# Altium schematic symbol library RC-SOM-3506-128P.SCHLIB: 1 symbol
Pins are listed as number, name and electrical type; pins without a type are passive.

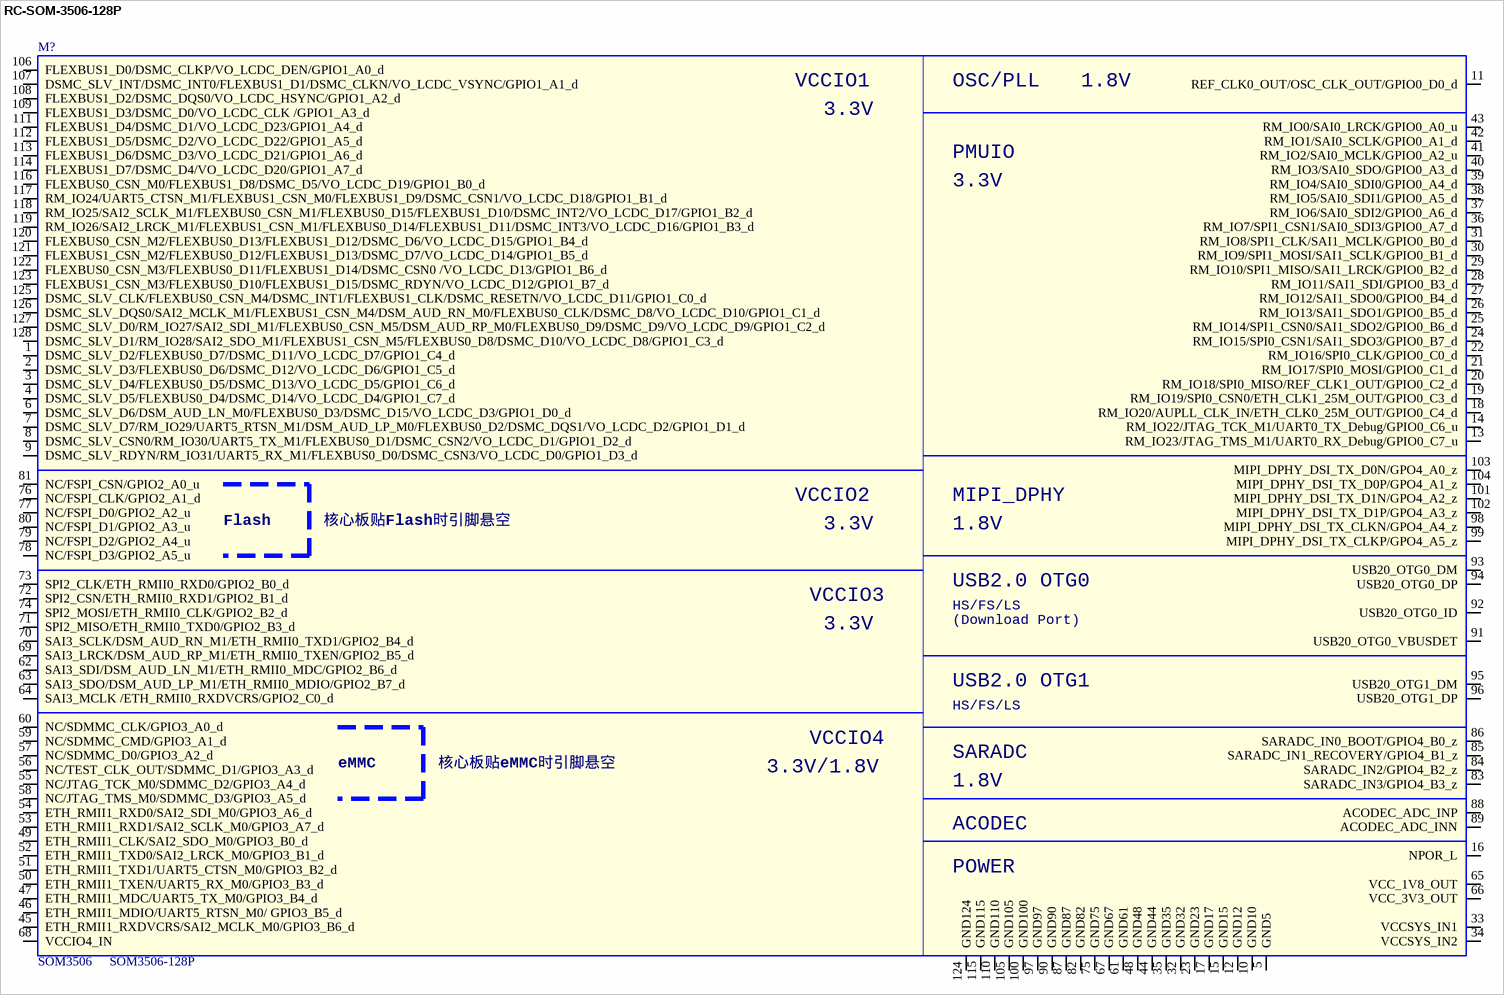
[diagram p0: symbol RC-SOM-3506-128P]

## RC-SOM-3506-128P
designator M?, comment SOM3506  PCB Footprint: SOM3506-128P
footprint SOM3506-128P
footprint SOM3506-128P
pins: 1 DSMC_SLV_D2/FLEXBUS0_D7/DSMC_D11/VO_LCDC_D7/GPIO1_C4_d, 2 DSMC_SLV_D3/FLEXBUS0_D6/DSMC_D12/VO_LCDC_D6/GPIO1_C5_d, 3 DSMC_SLV_D4/FLEXBUS0_D5/DSMC_D13/VO_LCDC_D5/GPIO1_C6_d, 4 DSMC_SLV_D5/FLEXBUS0_D4/DSMC_D14/VO_LCDC_D4/GPIO1_C7_d, 5 GND5, 6 DSMC_SLV_D6/DSM_AUD_LN_M0/FLEXBUS0_D3/DSMC_D15/VO_LCDC_D3/GPIO1_D0_d, 7 DSMC_SLV_D7/RM_IO29/UART5_RTSN_M1/DSM_AUD_LP_M0/FLEXBUS0_D2/DSMC_DQS1/VO_LCDC_D2/GPIO1_D1_d, 8 DSMC_SLV_CSN0/RM_IO30/UART5_TX_M1/FLEXBUS0_D1/DSMC_CSN2/VO_LCDC_D1/GPIO1_D2_d, 9 DSMC_SLV_RDYN/RM_IO31/UART5_RX_M1/FLEXBUS0_D0/DSMC_CSN3/VO_LCDC_D0/GPIO1_D3_d, 10 GND10, 11 REF_CLK0_OUT/OSC_CLK_OUT/GPIO0_D0_d, 12 GND12, 13 RM_IO23/JTAG_TMS_M1/UART0_RX_Debug/GPIO0_C7_u, 14 RM_IO22/JTAG_TCK_M1/UART0_TX_Debug/GPIO0_C6_u, 15 GND15, 16 NPOR_L, 17 GND17, 18 RM_IO20/AUPLL_CLK_IN/ETH_CLK0_25M_OUT/GPIO0_C4_d, 19 RM_IO19/SPI0_CSN0/ETH_CLK1_25M_OUT/GPIO0_C3_d, 20 RM_IO18/SPI0_MISO/REF_CLK1_OUT/GPIO0_C2_d, 21 RM_IO17/SPI0_MOSI/GPIO0_C1_d, 22 RM_IO16/SPI0_CLK/GPIO0_C0_d, 23 GND23, 24 RM_IO15/SPI0_CSN1/SAI1_SDO3/GPIO0_B7_d, 25 RM_IO14/SPI1_CSN0/SAI1_SDO2/GPIO0_B6_d, 26 RM_IO13/SAI1_SDO1/GPIO0_B5_d, 27 RM_IO12/SAI1_SDO0/GPIO0_B4_d, 28 RM_IO11/SAI1_SDI/GPIO0_B3_d, 29 RM_IO10/SPI1_MISO/SAI1_LRCK/GPIO0_B2_d, 30 RM_IO9/SPI1_MOSI/SAI1_SCLK/GPIO0_B1_d, 31 RM_IO8/SPI1_CLK/SAI1_MCLK/GPIO0_B0_d, 32 GND32, 33 VCCSYS_IN1, 34 VCCSYS_IN2, 35 GND35, 36 RM_IO7/SPI1_CSN1/SAI0_SDI3/GPIO0_A7_d, 37 RM_IO6/SAI0_SDI2/GPIO0_A6_d, 38 RM_IO5/SAI0_SDI1/GPIO0_A5_d, 39 RM_IO4/SAI0_SDI0/GPIO0_A4_d, 40 RM_IO3/SAI0_SDO/GPIO0_A3_d, 41 RM_IO2/SAI0_MCLK/GPIO0_A2_u, 42 RM_IO1/SAI0_SCLK/GPIO0_A1_d, 43 RM_IO0/SAI0_LRCK/GPIO0_A0_u, 44 GND44, 45 ETH_RMII1_RXDVCRS/SAI2_MCLK_M0/GPIO3_B6_d, 46 ETH_RMII1_MDIO/UART5_RTSN_M0/ GPIO3_B5_d, 47 ETH_RMII1_MDC/UART5_TX_M0/GPIO3_B4_d, 48 GND48, 49 ETH_RMII1_CLK/SAI2_SDO_M0/GPIO3_B0_d, 50 ETH_RMII1_TXEN/UART5_RX_M0/GPIO3_B3_d, 51 ETH_RMII1_TXD1/UART5_CTSN_M0/GPIO3_B2_d, 52 ETH_RMII1_TXD0/SAI2_LRCK_M0/GPIO3_B1_d, 53 ETH_RMII1_RXD1/SAI2_SCLK_M0/GPIO3_A7_d, 54 ETH_RMII1_RXD0/SAI2_SDI_M0/GPIO3_A6_d, 55 NC/JTAG_TCK_M0/SDMMC_D2/GPIO3_A4_d, 56 NC/TEST_CLK_OUT/SDMMC_D1/GPIO3_A3_d, 57 NC/SDMMC_D0/GPIO3_A2_d, 58 NC/JTAG_TMS_M0/SDMMC_D3/GPIO3_A5_d, 59 NC/SDMMC_CMD/GPIO3_A1_d, 60 NC/SDMMC_CLK/GPIO3_A0_d, 61 GND61, 62 SAI3_SDI/DSM_AUD_LN_M1/ETH_RMII0_MDC/GPIO2_B6_d, 63 SAI3_SDO/DSM_AUD_LP_M1/ETH_RMII0_MDIO/GPIO2_B7_d, 64 SAI3_MCLK /ETH_RMII0_RXDVCRS/GPIO2_C0_d, 65 VCC_1V8_OUT, 66 VCC_3V3_OUT, 67 GND67, 68 VCCIO4_IN, 69 SAI3_LRCK/DSM_AUD_RP_M1/ETH_RMII0_TXEN/GPIO2_B5_d, 70 SAI3_SCLK/DSM_AUD_RN_M1/ETH_RMII0_TXD1/GPIO2_B4_d, 71 SPI2_MISO/ETH_RMII0_TXD0/GPIO2_B3_d, 72 SPI2_CSN/ETH_RMII0_RXD1/GPIO2_B1_d, 73 SPI2_CLK/ETH_RMII0_RXD0/GPIO2_B0_d, 74 SPI2_MOSI/ETH_RMII0_CLK/GPIO2_B2_d, 75 GND75, 76 NC/FSPI_CLK/GPIO2_A1_d, 77 NC/FSPI_D0/GPIO2_A2_u, 78 NC/FSPI_D3/GPIO2_A5_u, 79 NC/FSPI_D2/GPIO2_A4_u, 80 NC/FSPI_D1/GPIO2_A3_u, 81 NC/FSPI_CSN/GPIO2_A0_u, 82 GND82, 83 SARADC_IN3/GPIO4_B3_z, 84 SARADC_IN2/GPIO4_B2_z, 85 SARADC_IN1_RECOVERY/GPIO4_B1_z, 86 SARADC_IN0_BOOT/GPIO4_B0_z, 87 GND87, 88 ACODEC_ADC_INP, 89 ACODEC_ADC_INN, 90 GND90, 91 USB20_OTG0_VBUSDET, 92 USB20_OTG0_ID, 93 USB20_OTG0_DM, 94 USB20_OTG0_DP, 95 USB20_OTG1_DM, 96 USB20_OTG1_DP, 97 GND97, 98 MIPI_DPHY_DSI_TX_CLKN/GPO4_A4_z, 99 MIPI_DPHY_DSI_TX_CLKP/GPO4_A5_z, 100 GND100, 101 MIPI_DPHY_DSI_TX_D1N/GPO4_A2_z, 102 MIPI_DPHY_DSI_TX_D1P/GPO4_A3_z, 103 MIPI_DPHY_DSI_TX_D0N/GPO4_A0_z, 104 MIPI_DPHY_DSI_TX_D0P/GPO4_A1_z, 105 GND105, 106 FLEXBUS1_D0/DSMC_CLKP/VO_LCDC_DEN/GPIO1_A0_d, 107 DSMC_SLV_INT/DSMC_INT0/FLEXBUS1_D1/DSMC_CLKN/VO_LCDC_VSYNC/GPIO1_A1_d, 108 FLEXBUS1_D2/DSMC_DQS0/VO_LCDC_HSYNC/GPIO1_A2_d, 109 FLEXBUS1_D3/DSMC_D0/VO_LCDC_CLK /GPIO1_A3_d, 110 GND110, 111 FLEXBUS1_D4/DSMC_D1/VO_LCDC_D23/GPIO1_A4_d, 112 FLEXBUS1_D5/DSMC_D2/VO_LCDC_D22/GPIO1_A5_d, 113 FLEXBUS1_D6/DSMC_D3/VO_LCDC_D21/GPIO1_A6_d, 114 FLEXBUS1_D7/DSMC_D4/VO_LCDC_D20/GPIO1_A7_d, 115 GND115, 116 FLEXBUS0_CSN_M0/FLEXBUS1_D8/DSMC_D5/VO_LCDC_D19/GPIO1_B0_d, 117 RM_IO24/UART5_CTSN_M1/FLEXBUS1_CSN_M0/FLEXBUS1_D9/DSMC_CSN1/VO_LCDC_D18/GPIO1_B1_d, 118 RM_IO25/SAI2_SCLK_M1/FLEXBUS0_CSN_M1/FLEXBUS0_D15/FLEXBUS1_D10/DSMC_INT2/VO_LCDC_D17/GPIO1_B2_d, 119 RM_IO26/SAI2_LRCK_M1/FLEXBUS1_CSN_M1/FLEXBUS0_D14/FLEXBUS1_D11/DSMC_INT3/VO_LCDC_D16/GPIO1_B3_d, 120 FLEXBUS0_CSN_M2/FLEXBUS0_D13/FLEXBUS1_D12/DSMC_D6/VO_LCDC_D15/GPIO1_B4_d, 121 FLEXBUS1_CSN_M2/FLEXBUS0_D12/FLEXBUS1_D13/DSMC_D7/VO_LCDC_D14/GPIO1_B5_d, 122 FLEXBUS0_CSN_M3/FLEXBUS0_D11/FLEXBUS1_D14/DSMC_CSN0 /VO_LCDC_D13/GPIO1_B6_d, 123 FLEXBUS1_CSN_M3/FLEXBUS0_D10/FLEXBUS1_D15/DSMC_RDYN/VO_LCDC_D12/GPIO1_B7_d, 124 GND124, 125 DSMC_SLV_CLK/FLEXBUS0_CSN_M4/DSMC_INT1/FLEXBUS1_CLK/DSMC_RESETN/VO_LCDC_D11/GPIO1_C0_d, 126 DSMC_SLV_DQS0/SAI2_MCLK_M1/FLEXBUS1_CSN_M4/DSM_AUD_RN_M0/FLEXBUS0_CLK/DSMC_D8/VO_LCDC_D10/GPIO1_C1_d, 127 DSMC_SLV_D0/RM_IO27/SAI2_SDI_M1/FLEXBUS0_CSN_M5/DSM_AUD_RP_M0/FLEXBUS0_D9/DSMC_D9/VO_LCDC_D9/GPIO1_C2_d, 128 DSMC_SLV_D1/RM_IO28/SAI2_SDO_M1/FLEXBUS1_CSN_M5/FLEXBUS0_D8/DSMC_D10/VO_LCDC_D8/GPIO1_C3_d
